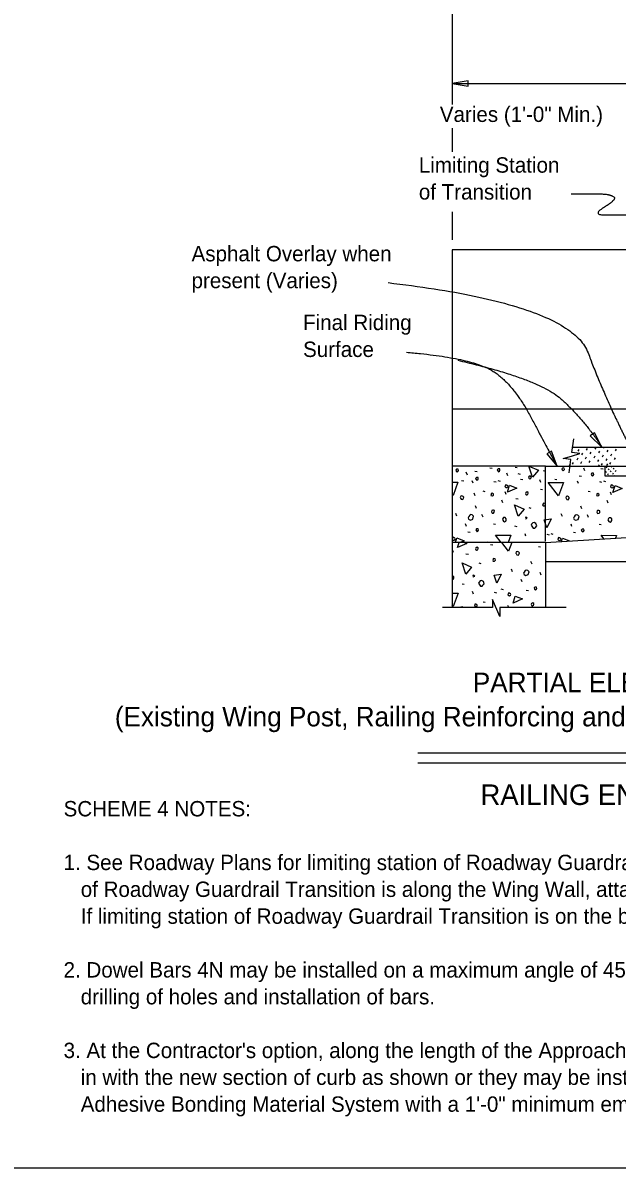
# Model space of a CAD drawing. Extents: x 1.5 to 68.7, y 0 to 31.1.
# Drawn here: x 20.65 to 28.44, y 1.78 to 16.79 of the extents above; entities that cross this region are included whole.
import ezdxf

# ---------------------------------------------------------------- set-up
doc = ezdxf.new("R2010")
doc.units = 0
for name, color, linetype in [('ActivePts-ConstElements', 7, 'Continuous'), ('Dimension', 7, 'Continuous'), ('Miscellaneous', 7, 'Continuous'), ('TextStructures', 7, 'Continuous'), ('TrafBarrierConc', 7, 'Continuous')]:
    doc.layers.add(name, color=color, linetype=linetype)

msp = doc.modelspace()

# ---------------------------------------------------------------- linework, layer by layer
at = {"layer": 'ActivePts-ConstElements'}
msp.add_lwpolyline([(1.467, 28.183), (42.533, 28.183), (42.533, 1.783), (1.467, 1.783)], close=True, dxfattribs=at)
at = {"layer": 'Dimension'}
for p, q in [((26.277, 20.091), (26.277, 15.724)), ((26.277, 15.416), (26.277, 15.106)), ((26.277, 14.316), (26.277, 13.949)), ((30.085, 7.224), (25.826, 7.224)), ((30.085, 7.091), (25.826, 7.091))]:
    msp.add_line(p, q, dxfattribs=at)
for points in [[(26.277, 15.998), (26.485, 15.963), (26.485, 16.033)], [(28.238, 11.235), (28.141, 11.423), (28.085, 11.381)], [(27.652, 10.983), (27.579, 11.181), (27.518, 11.146)]]:
    msp.add_lwpolyline(points, close=True, dxfattribs=at)
for points in [[(26.277, 15.998), (29.811, 15.998)], [(27.809, 10.898), (27.832, 11.072), (27.73, 11.086), (27.838, 11.117), (27.947, 11.148), (27.844, 11.161), (27.869, 11.344)], [(27.77, 9.13), (26.901, 9.13), (26.901, 9.013), (26.802, 9.238), (26.802, 9.13), (26.146, 9.13)]]:
    msp.add_lwpolyline(points, dxfattribs=at)
for points in [[(27.836, 14.553), (28.073, 14.553), (28.329, 14.553), (28.447, 14.486), (28.102, 14.277), (28.44, 14.277), (28.701, 14.277)], [(25.434, 13.39), (27.814, 13.112), (28.299, 11.826), (28.608, 11.234)], [(25.677, 12.477), (26.504, 12.407), (27.069, 12.08), (27.575, 11.117), (27.652, 10.983)], [(26.348, 12.372), (27.415, 12.129), (28.009, 11.586), (28.238, 11.235)]]:
    msp.add_open_spline(points, degree=2, dxfattribs=at)
at = {"layer": 'Miscellaneous'}
for p, q in [((27.878, 11.229), (27.881, 11.234)), ((27.927, 11.18), (27.94, 11.202)), ((27.975, 11.131), (27.988, 11.154)), ((28.037, 11.193), (28.05, 11.215)), ((28.086, 11.144), (28.099, 11.167)), ((28.135, 11.095), (28.148, 11.118)), ((28.148, 11.206), (28.161, 11.228)), ((28.197, 11.157), (28.21, 11.18)), ((28.245, 11.108), (28.258, 11.131)), ((28.258, 11.219), (28.267, 11.234)), ((28.307, 11.17), (28.32, 11.193)), ((28.356, 11.121), (28.369, 11.144)), ((28.369, 11.232), (28.371, 11.234)), ((28.418, 11.183), (28.431, 11.205)), ((26.77, 10.962), (26.8, 10.957)), ((27.099, 10.97), (27.129, 10.965)), ((27.812, 10.988), (27.825, 11.01)), ((27.852, 11.008), (27.865, 11.03)), ((27.914, 11.069), (27.927, 11.092)), ((27.962, 11.021), (27.975, 11.043)), ((28.024, 11.082), (28.037, 11.105)), ((28.073, 11.034), (28.086, 11.056)), ((28.184, 11.047), (28.197, 11.069)), ((28.194, 10.982), (28.205, 11)), ((28.233, 10.998), (28.245, 11.02)), ((28.294, 11.059), (28.307, 11.082)), ((28.298, 10.964), (28.306, 10.978)), ((28.303, 10.991), (28.316, 11.013)), ((28.343, 11.011), (28.356, 11.033)), ((28.361, 10.972), (28.368, 10.984)), ((28.399, 10.983), (28.4, 10.984)), ((28.405, 11.072), (28.418, 11.095)), ((28.425, 10.98), (28.427, 10.984)), ((26.474, 10.868), (26.46, 10.904)), ((26.574, 10.918), (26.604, 10.912)), ((27.007, 10.856), (26.993, 10.892)), ((27.135, 10.886), (27.165, 10.88)), ((27.171, 10.814), (27.201, 10.808)), ((27.467, 10.926), (27.497, 10.92)), ((27.619, 10.814), (27.649, 10.808)), ((27.94, 10.858), (27.97, 10.852)), ((28.016, 10.921), (28.002, 10.956)), ((28.224, 10.954), (28.254, 10.949)), ((28.289, 10.9), (28.298, 10.914)), ((28.317, 10.872), (28.325, 10.886)), ((28.325, 10.936), (28.333, 10.95)), ((28.353, 10.908), (28.361, 10.922)), ((28.381, 10.881), (28.389, 10.895)), ((28.389, 10.944), (28.397, 10.958)), ((28.412, 10.859), (28.416, 10.867)), ((28.416, 10.916), (28.425, 10.93)), ((26.398, 10.797), (26.428, 10.792)), ((26.549, 10.759), (26.537, 10.792)), ((26.677, 10.66), (26.703, 10.654)), ((26.823, 10.785), (26.852, 10.778)), ((26.875, 10.795), (26.903, 10.787)), ((27.439, 10.768), (27.425, 10.804)), ((27.434, 10.681), (27.461, 10.676)), ((27.933, 10.755), (27.92, 10.789)), ((28.207, 10.782), (28.235, 10.775)), ((28.258, 10.791), (28.287, 10.784)), ((26.578, 10.596), (26.564, 10.631)), ((26.939, 10.504), (26.925, 10.539)), ((26.981, 10.613), (26.969, 10.647)), ((27.111, 10.559), (27.142, 10.555)), ((28.06, 10.656), (28.086, 10.651)), ((28.322, 10.5), (28.308, 10.536)), ((28.364, 10.61), (28.352, 10.643)), ((26.337, 10.327), (26.323, 10.363)), ((26.594, 10.428), (26.579, 10.464)), ((27.279, 10.441), (27.307, 10.433)), ((27.72, 10.324), (27.706, 10.359)), ((27.977, 10.425), (27.963, 10.46)), ((26.463, 10.195), (26.45, 10.228)), ((26.681, 10.316), (26.666, 10.352)), ((26.818, 10.228), (26.843, 10.224)), ((27.846, 10.191), (27.834, 10.225)), ((28.064, 10.313), (28.05, 10.348)), ((28.202, 10.224), (28.227, 10.221)), ((26.481, 10.124), (26.511, 10.118)), ((27.094, 10.2), (27.124, 10.194)), ((27.243, 10.065), (27.23, 10.099)), ((27.517, 10.092), (27.545, 10.085)), ((27.568, 10.101), (27.597, 10.094)), ((27.864, 10.12), (27.894, 10.115)), ((26.744, 9.991), (26.771, 9.986)), ((26.744, 9.991), (26.771, 9.986)), ((26.779, 9.956), (26.806, 9.951)), ((27.405, 9.931), (27.431, 9.926)), ((26.291, 9.854), (26.279, 9.887)), ((26.456, 9.834), (26.487, 9.831)), ((26.624, 9.716), (26.652, 9.709)), ((27.066, 9.599), (27.051, 9.634)), ((27.322, 9.7), (27.308, 9.735)), ((27.191, 9.466), (27.179, 9.5)), ((27.444, 9.553), (27.43, 9.588)), ((26.404, 9.44), (26.434, 9.435)), ((26.553, 9.306), (26.54, 9.339)), ((26.827, 9.332), (26.855, 9.325)), ((26.913, 9.376), (26.942, 9.369)), ((27.244, 9.36), (27.274, 9.355)), ((26.68, 9.207), (26.707, 9.201)), ((27.018, 9.13), (27.007, 9.159))]:
    msp.add_line(p, q, dxfattribs=at)
for points in [[(27.33, 10.838), (27.282, 10.984), (27.408, 10.93), (27.33, 10.838)], [(27.719, 10.934), (27.729, 10.924), (27.74, 10.931), (27.747, 10.941), (27.743, 10.959), (27.735, 10.961), (27.722, 10.959), (27.712, 10.948), (27.719, 10.934)], [(26.329, 10.918), (26.34, 10.907), (26.35, 10.915), (26.357, 10.925), (26.354, 10.943), (26.345, 10.945), (26.332, 10.943), (26.322, 10.932), (26.329, 10.918)], [(26.589, 10.81), (26.6, 10.799), (26.61, 10.806), (26.618, 10.817), (26.614, 10.835), (26.605, 10.836), (26.593, 10.835), (26.582, 10.824), (26.589, 10.81)], [(26.874, 10.922), (26.884, 10.911), (26.895, 10.919), (26.902, 10.929), (26.898, 10.947), (26.889, 10.949), (26.877, 10.947), (26.867, 10.936), (26.874, 10.922)], [(27.282, 10.826), (27.293, 10.815), (27.303, 10.822), (27.31, 10.833), (27.307, 10.851), (27.298, 10.852), (27.286, 10.851), (27.275, 10.84), (27.282, 10.826)], [(28.103, 10.866), (28.114, 10.855), (28.124, 10.862), (28.131, 10.873), (28.128, 10.891), (28.119, 10.893), (28.107, 10.891), (28.096, 10.88), (28.103, 10.866)], [(26.277, 10.774), (26.351, 10.773), (26.286, 10.598)], [(26.978, 10.706), (26.99, 10.704), (27.002, 10.71), (27.006, 10.72), (27.001, 10.729), (26.99, 10.736), (26.978, 10.741), (26.971, 10.727), (26.967, 10.717), (26.978, 10.706)], [(26.999, 10.642), (27.028, 10.734), (27.121, 10.697), (26.999, 10.642)], [(27.669, 10.594), (27.535, 10.771), (27.735, 10.769), (27.669, 10.594)], [(28.361, 10.703), (28.373, 10.701), (28.386, 10.706), (28.389, 10.717), (28.384, 10.726), (28.373, 10.733), (28.361, 10.738), (28.354, 10.724), (28.35, 10.713), (28.361, 10.703)], [(28.383, 10.639), (28.411, 10.73), (28.505, 10.693), (28.383, 10.639)], [(26.286, 10.598), (26.277, 10.609)], [(26.385, 10.566), (26.394, 10.55), (26.415, 10.547), (26.424, 10.563), (26.427, 10.577), (26.419, 10.585), (26.403, 10.594), (26.387, 10.589), (26.381, 10.573), (26.385, 10.566)], [(26.784, 10.601), (26.804, 10.596), (26.816, 10.605), (26.818, 10.617), (26.815, 10.621), (26.8, 10.628), (26.788, 10.626), (26.786, 10.614), (26.784, 10.601)], [(27.247, 10.607), (27.254, 10.607), (27.268, 10.614), (27.273, 10.63), (27.271, 10.639), (27.257, 10.646), (27.24, 10.635), (27.236, 10.624), (27.24, 10.614), (27.247, 10.607)], [(27.768, 10.563), (27.777, 10.547), (27.798, 10.543), (27.807, 10.559), (27.811, 10.573), (27.802, 10.582), (27.786, 10.591), (27.77, 10.585), (27.765, 10.57), (27.768, 10.563)], [(28.168, 10.598), (28.187, 10.593), (28.2, 10.601), (28.201, 10.614), (28.198, 10.617), (28.184, 10.624), (28.171, 10.623), (28.17, 10.61), (28.168, 10.598)], [(26.79, 10.384), (26.799, 10.368), (26.818, 10.369), (26.827, 10.382), (26.829, 10.401), (26.817, 10.406), (26.808, 10.408), (26.797, 10.405), (26.794, 10.401), (26.79, 10.384)], [(27.142, 10.329), (27.094, 10.475), (27.22, 10.421), (27.142, 10.329)], [(27.466, 10.465), (27.487, 10.465), (27.498, 10.476), (27.492, 10.495), (27.469, 10.497), (27.466, 10.486), (27.461, 10.478), (27.466, 10.465), (27.462, 10.469)], [(28.173, 10.38), (28.182, 10.364), (28.202, 10.366), (28.211, 10.378), (28.212, 10.398), (28.2, 10.403), (28.191, 10.405), (28.181, 10.401), (28.177, 10.398), (28.173, 10.38)], [(26.491, 10.29), (26.514, 10.278), (26.544, 10.29), (26.556, 10.327), (26.539, 10.345), (26.516, 10.35), (26.505, 10.343), (26.493, 10.324), (26.484, 10.308), (26.491, 10.29)], [(26.935, 10.285), (26.946, 10.263), (26.963, 10.253), (26.978, 10.263), (26.985, 10.274), (26.985, 10.295), (26.969, 10.311), (26.949, 10.309), (26.94, 10.3), (26.935, 10.285)], [(27.241, 10.293), (27.26, 10.302), (27.253, 10.309), (27.241, 10.315), (27.236, 10.302), (27.241, 10.293)], [(27.312, 10.209), (27.335, 10.171), (27.358, 10.173), (27.367, 10.182), (27.386, 10.201), (27.374, 10.231), (27.349, 10.246), (27.331, 10.239), (27.317, 10.224), (27.312, 10.209)], [(27.514, 10.177), (27.48, 10.281), (27.574, 10.294), (27.514, 10.177)], [(27.874, 10.287), (27.897, 10.274), (27.927, 10.287), (27.94, 10.324), (27.922, 10.342), (27.899, 10.347), (27.888, 10.34), (27.876, 10.32), (27.867, 10.304), (27.874, 10.287)], [(28.318, 10.281), (28.329, 10.26), (28.347, 10.249), (28.361, 10.26), (28.368, 10.27), (28.368, 10.292), (28.352, 10.308), (28.333, 10.306), (28.324, 10.297), (28.318, 10.281)], [(26.592, 10.136), (26.603, 10.125), (26.613, 10.132), (26.621, 10.143), (26.617, 10.161), (26.608, 10.163), (26.596, 10.161), (26.585, 10.15), (26.592, 10.136)], [(26.919, 9.984), (26.845, 10.081), (27.045, 10.079), (27.009, 9.984)], [(27.975, 10.132), (27.986, 10.122), (27.997, 10.129), (28.004, 10.14), (28, 10.157), (27.991, 10.159), (27.979, 10.157), (27.968, 10.147), (27.975, 10.132)], [(28.263, 10.032), (28.228, 10.078), (28.428, 10.076), (28.415, 10.042)], [(26.288, 10.016), (26.3, 10.014), (26.312, 10.02), (26.316, 10.03), (26.311, 10.039), (26.3, 10.046), (26.288, 10.052), (26.281, 10.037), (26.277, 10.027)], [(26.277, 10.027), (26.288, 10.016)], [(26.319, 9.984), (26.338, 10.044), (26.431, 10.007), (26.381, 9.984)], [(26.344, 9.917), (26.365, 9.984)], [(26.435, 9.984), (26.466, 9.972), (26.344, 9.917)], [(26.592, 9.882), (26.599, 9.882), (26.613, 9.889), (26.618, 9.905), (26.616, 9.914), (26.602, 9.921), (26.585, 9.91), (26.581, 9.9), (26.585, 9.889), (26.592, 9.882)], [(27.014, 9.87), (26.927, 9.984)], [(27.057, 9.984), (27.014, 9.87)], [(27.671, 10.013), (27.683, 10.011), (27.696, 10.016), (27.699, 10.027), (27.694, 10.036), (27.683, 10.043), (27.671, 10.048), (27.664, 10.034), (27.66, 10.023), (27.671, 10.013)], [(27.708, 9.998), (27.721, 10.041), (27.813, 10.004)], [(26.811, 9.74), (26.832, 9.74), (26.843, 9.751), (26.837, 9.771), (26.814, 9.772), (26.811, 9.762), (26.806, 9.753), (26.811, 9.74), (26.807, 9.744)], [(27.113, 9.838), (27.122, 9.822), (27.143, 9.818), (27.152, 9.834), (27.156, 9.848), (27.147, 9.857), (27.131, 9.866), (27.115, 9.861), (27.11, 9.845), (27.113, 9.838)], [(26.452, 9.569), (26.404, 9.716), (26.53, 9.661), (26.452, 9.569)], [(27.219, 9.562), (27.242, 9.55), (27.272, 9.562), (27.285, 9.599), (27.267, 9.617), (27.244, 9.622), (27.233, 9.615), (27.221, 9.596), (27.212, 9.58), (27.219, 9.562)], [(26.277, 9.496), (26.288, 9.504), (26.295, 9.514), (26.295, 9.535), (26.279, 9.551), (26.277, 9.551)], [(26.551, 9.534), (26.571, 9.543), (26.563, 9.55), (26.551, 9.555), (26.546, 9.543), (26.551, 9.534)], [(26.622, 9.449), (26.645, 9.412), (26.668, 9.413), (26.677, 9.422), (26.696, 9.442), (26.684, 9.472), (26.659, 9.486), (26.641, 9.479), (26.627, 9.465), (26.622, 9.449)], [(26.859, 9.452), (26.825, 9.557), (26.919, 9.569), (26.859, 9.452)], [(26.277, 9.32), (26.355, 9.32), (26.289, 9.145)], [(27.016, 9.288), (27.028, 9.286), (27.041, 9.291), (27.044, 9.302), (27.039, 9.311), (27.028, 9.318), (27.016, 9.323), (27.009, 9.309), (27.005, 9.299), (27.016, 9.288)], [(27.355, 9.373), (27.366, 9.362), (27.377, 9.369), (27.384, 9.38), (27.38, 9.398), (27.371, 9.399), (27.359, 9.398), (27.348, 9.387), (27.355, 9.373)], [(26.289, 9.145), (26.277, 9.161)], [(26.569, 9.148), (26.588, 9.143), (26.601, 9.152), (26.603, 9.164), (26.599, 9.168), (26.585, 9.175), (26.572, 9.173), (26.571, 9.161), (26.569, 9.148)], [(27.073, 9.189), (27.101, 9.281), (27.195, 9.244), (27.073, 9.189)], [(27.32, 9.154), (27.327, 9.154), (27.341, 9.161), (27.347, 9.177), (27.345, 9.185), (27.331, 9.192), (27.313, 9.182), (27.309, 9.171), (27.313, 9.161), (27.32, 9.154)], [(26.425, 9.13), (26.422, 9.132), (26.406, 9.141), (26.39, 9.136), (26.388, 9.13)]]:
    msp.add_lwpolyline(points, dxfattribs=at)
at = {"layer": 'TrafBarrierConc'}
for p, q in [((26.277, 13.818), (26.277, 11.734)), ((36.552, 13.818), (26.277, 13.818)), ((26.277, 11.734), (36.676, 11.734)), ((26.277, 11.734), (26.277, 10.984)), ((27.854, 11.234), (30.116, 11.234)), ((26.277, 10.984), (26.277, 9.13)), ((27.497, 10.984), (26.277, 10.984)), ((27.497, 10.003), (27.497, 10.984)), ((27.497, 10.984), (37.698, 10.984)), ((28.277, 10.984), (28.277, 10.859)), ((28.277, 10.859), (34.222, 10.859)), ((27.497, 9.984), (31.497, 10.234)), ((27.497, 9.984), (26.277, 9.984)), ((27.497, 9.984), (27.497, 9.13)), ((27.497, 9.984), (27.497, 9.13)), ((27.497, 9.984), (27.497, 9.734)), ((27.497, 9.734), (36.676, 9.734))]:
    msp.add_line(p, q, dxfattribs=at)

# ---------------------------------------------------------------- texts
at = {"layer": 'Dimension'}
for s, height, p in [('Limiting Station ', 0.2016, (25.838, 14.831)), ('of Transition', 0.2016, (25.838, 14.479)), ('Asphalt Overlay when ', 0.2016, (22.858, 13.669)), ('present (Varies)', 0.2016, (22.858, 13.317)), ('Final Riding ', 0.2016, (24.32, 12.767)), ('Surface', 0.2016, (24.32, 12.415)), ('PARTIAL ELEVATION OF INSIDE FACE OF RAILING', 0.256, (26.546, 8.021)), ('(Existing Wing Post, Railing Reinforcing and Expansion Dowel Assemblies not shown for clarity)', 0.256, (21.852, 7.573)), ('RAILING END TREATMENT FOR FLARED CURBS', 0.2688, (26.647, 6.543)), ('SCHEME 4 NOTES:', 0.2016, (21.18, 6.393)), ('1. See Roadway Plans for limiting station of Roadway Guardrail Transition or other site specific treatment.  If limiting station ', 0.2016, (21.18, 5.689)), ('   of Roadway Guardrail Transition is along the Wing Wall, attach Thrie-Beam Terminal Connector to railing as shown above.  ', 0.2016, (21.18, 5.337)), ('   If limiting station of Roadway Guardrail Transition is on the bridge, see Sheet 3 of 6.', 0.2016, (21.18, 4.985)), ('2. Dowel Bars 4N may be installed on a maximum angle of 45° to the cut edge of the Approach Slab as shown to facilitate ', 0.2016, (21.18, 4.281)), ('   drilling of holes and installation of bars.', 0.2016, (21.18, 3.929)), ("3. At the Contractor's option, along the length of the Approach Slab curb that is to be replaced, Dowel Bars 6D may be cast ", 0.2016, (21.18, 3.225)), ('   in with the new section of curb as shown or they may be installed in drilled holes in the new section of curb using an ', 0.2016, (21.18, 2.873)), ('   Adhesive Bonding Material System with a 1\'-0" minimum embedment. ', 0.2016, (21.18, 2.521))]:
    msp.add_text(s, height=height, dxfattribs=at).set_placement(p)
at = {"layer": 'TextStructures'}
msp.add_text('Varies (1\'-0" Min.)', height=0.2016, dxfattribs=at).set_placement((26.113, 15.496))

doc.saveas('drawing.dxf')
